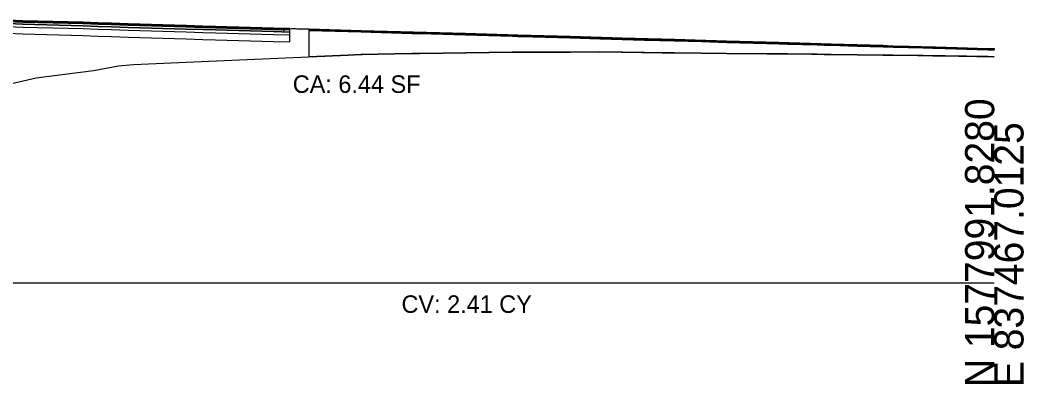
# Model space of a CAD drawing. Extents: x -26 to 6303, y -16 to 9563.
# Drawn here: x 2206.7 to 2302.8, y 4490.3 to 4525.2 of the extents above; entities that cross this region are included whole.
import ezdxf

# ---------------------------------------------------------------- set-up
doc = ezdxf.new("R2010")
doc.units = 0
for name, color, linetype in [('ASPHALT_19MM1', 7, 'Continuous'), ('ASPHALT_9_5MM1', 7, 'Continuous'), ('CONST_LV3', 7, 'Continuous'), ('Default', 7, 'Continuous'), ('DTM_P_FINISHED_GRADE', 7, 'Continuous'), ('DTM_P_FINISHED_GRADE2', 7, 'Continuous'), ('DTM_X_GROUND', 7, 'Continuous'), ('TRANS_PAVED_SHOULDERS', 7, 'Continuous'), ('XS_CELL', 7, 'Continuous'), ('XS_P_ASPHALT', 7, 'Continuous'), ('XS_P_SUBGRADE_GRANULAR', 7, 'Continuous'), ('XS_P_SUBGRADE_LEVELING', 7, 'Continuous'), ('XS_P_SUBGRADE_MILLING', 7, 'Continuous'), ('XS_SHEET_EW_TX_AREA', 7, 'Continuous'), ('XS_SHEET_EW_TX_VOLUME', 7, 'Continuous')]:
    doc.layers.add(name, color=color, linetype=linetype)

msp = doc.modelspace()

# ---------------------------------------------------------------- linework, layer by layer
at = {"layer": 'ASPHALT_19MM1'}
msp.add_lwpolyline([(2205.518, 4524.596), (2206.933, 4524.534), (2212.712, 4524.379), (2214.156, 4524.319), (2215.418, 4524.285), (2217.029, 4524.225), (2222.562, 4524.067), (2224.176, 4524.012), (2225.395, 4523.977), (2230.925, 4523.82), (2232.513, 4523.772), (2232.513, 4524.043), (2230.925, 4524.091), (2225.395, 4524.248), (2224.176, 4524.283), (2222.562, 4524.338), (2217.029, 4524.495), (2215.418, 4524.556), (2214.156, 4524.59), (2212.712, 4524.65), (2206.933, 4524.805), (2205.518, 4524.867)], dxfattribs=at)
at = {"layer": 'ASPHALT_9_5MM1'}
msp.add_lwpolyline([(2205.518, 4525.075), (2206.933, 4525.013), (2212.712, 4524.858), (2214.156, 4524.798), (2215.418, 4524.764), (2217.029, 4524.704), (2222.562, 4524.546), (2224.176, 4524.491), (2225.395, 4524.457), (2230.925, 4524.3), (2232.513, 4524.251), (2232.513, 4524.376), (2230.925, 4524.425), (2225.395, 4524.582), (2224.176, 4524.616), (2222.562, 4524.671), (2217.029, 4524.829), (2215.418, 4524.889), (2214.156, 4524.923), (2212.712, 4524.983), (2206.933, 4525.138), (2205.518, 4525.2)], dxfattribs=at)
at = {"layer": 'CONST_LV3'}
for points in [[(2205.518, 4523.928), (2206.933, 4523.867), (2212.712, 4523.711), (2214.156, 4523.651), (2215.418, 4523.618), (2217.029, 4523.557), (2222.562, 4523.4), (2224.176, 4523.345), (2225.395, 4523.31), (2230.925, 4523.153), (2232.513, 4523.105), (2232.513, 4524.376), (2230.925, 4524.424), (2225.395, 4524.581), (2224.176, 4524.615), (2222.562, 4524.671), (2217.029, 4524.828), (2215.418, 4524.888), (2214.156, 4524.922), (2212.712, 4524.982), (2206.933, 4525.137), (2205.518, 4525.199)], [(2289.363, 4522.762), (2284.361, 4522.904), (2279.359, 4523.046), (2274.357, 4523.188), (2269.355, 4523.33), (2264.353, 4523.472), (2259.351, 4523.614), (2254.349, 4523.756), (2249.347, 4523.898), (2244.345, 4524.04), (2239.343, 4524.182), (2234.341, 4524.324), (2233.08, 4524.359), (2232.662, 4524.371)]]:
    msp.add_lwpolyline(points, dxfattribs=at)
at = {"layer": 'Default'}
msp.add_lwpolyline([(2205.703, 4525.191), (2206.839, 4525.141), (2206.906, 4525.139), (2206.922, 4525.138), (2211.933, 4525.003), (2211.942, 4525.003), (2212.357, 4524.985), (2213.316, 4524.946), (2215.325, 4524.892), (2215.374, 4524.89), (2215.399, 4524.889), (2215.415, 4524.889), (2215.418, 4524.888), (2215.421, 4524.888), (2215.962, 4524.868), (2216.925, 4524.832), (2221.73, 4524.695), (2221.763, 4524.694), (2221.797, 4524.693), (2221.824, 4524.692), (2221.829, 4524.691), (2222.422, 4524.671), (2224.391, 4524.615), (2225.294, 4524.584), (2225.312, 4524.584), (2225.357, 4524.582), (2225.395, 4524.581), (2225.402, 4524.581), (2226.049, 4524.561), (2230.799, 4524.426), (2231.689, 4524.399), (2231.948, 4524.124)], dxfattribs=at)
at = {"layer": 'DTM_P_FINISHED_GRADE'}
msp.add_lwpolyline([(2205.518, 4525.199), (2206.933, 4525.137), (2212.712, 4524.982), (2214.156, 4524.922), (2215.418, 4524.888), (2217.029, 4524.828), (2222.562, 4524.671), (2224.176, 4524.615), (2225.395, 4524.581), (2230.925, 4524.424), (2232.513, 4524.376)], dxfattribs=at)
at = {"layer": 'DTM_P_FINISHED_GRADE2'}
msp.add_lwpolyline([(2205.518, 4525.199), (2206.933, 4525.137), (2212.712, 4524.982), (2214.156, 4524.922), (2215.418, 4524.888), (2217.029, 4524.828), (2222.562, 4524.671), (2224.176, 4524.615), (2225.395, 4524.581), (2228.11, 4524.5), (2233.187, 4524.356), (2234.341, 4524.324), (2236.216, 4524.27), (2239.343, 4524.182), (2241.232, 4524.128), (2244.345, 4524.04), (2246.249, 4523.986), (2249.347, 4523.898), (2251.267, 4523.843), (2254.349, 4523.756), (2256.286, 4523.701), (2259.351, 4523.614), (2261.306, 4523.558), (2264.353, 4523.472), (2266.328, 4523.416), (2269.355, 4523.33), (2271.346, 4523.274), (2274.347, 4523.188), (2274.351, 4523.188), (2274.357, 4523.188), (2276.375, 4523.131), (2279.359, 4523.046), (2280.851, 4523.004), (2283.04, 4522.942), (2283.573, 4522.927), (2284.361, 4522.904), (2286.429, 4522.846), (2289.363, 4522.762), (2289.747, 4522.751), (2290.301, 4522.736), (2291.882, 4522.691), (2294.115, 4522.627), (2294.217, 4522.625), (2294.365, 4522.62), (2296.459, 4522.561), (2299.367, 4522.478), (2300, 4522.46)], dxfattribs=at)
at = {"layer": 'DTM_X_GROUND'}
msp.add_lwpolyline([(2202.494, 4518.344), (2208.213, 4519.659), (2213.693, 4520.348), (2216.074, 4520.818), (2217.532, 4520.928), (2225.47, 4521.3), (2240.158, 4521.927), (2244.958, 4521.996), (2253.791, 4522.123), (2262.284, 4522.14), (2268.168, 4522.07), (2275.761, 4521.98), (2277.482, 4521.98), (2280.174, 4521.948), (2287.13, 4521.866), (2288.303, 4521.852), (2294.891, 4521.774), (2298.324, 4521.715), (2300, 4521.682)], dxfattribs=at)
at = {"layer": 'TRANS_PAVED_SHOULDERS'}
msp.add_lwpolyline([(2205.518, 4524.867), (2206.933, 4524.805), (2212.712, 4524.65), (2214.156, 4524.59), (2215.418, 4524.556), (2217.029, 4524.495), (2222.562, 4524.338), (2224.176, 4524.283), (2225.395, 4524.248), (2230.925, 4524.091), (2232.513, 4524.043), (2232.513, 4524.251), (2230.925, 4524.3), (2225.395, 4524.457), (2224.176, 4524.491), (2222.562, 4524.546), (2217.029, 4524.704), (2215.418, 4524.764), (2214.156, 4524.798), (2212.712, 4524.858), (2206.933, 4525.013), (2205.518, 4525.075)], dxfattribs=at)
at = {"layer": 'XS_CELL'}
msp.add_line((2150, 4500), (2300, 4500), dxfattribs=at)
at = {"layer": 'XS_P_ASPHALT'}
for points in [[(2205.518, 4525.199), (2206.933, 4525.137), (2212.712, 4524.982), (2214.156, 4524.922), (2215.418, 4524.888), (2217.029, 4524.828), (2222.562, 4524.671), (2224.176, 4524.615), (2225.395, 4524.581), (2230.925, 4524.424), (2232.513, 4524.376)], [(2300, 4522.46), (2300, 4522.335), (2300, 4522.335), (2299.367, 4522.353), (2299.367, 4522.353), (2296.459, 4522.436), (2296.459, 4522.436), (2294.365, 4522.495), (2294.365, 4522.495), (2294.217, 4522.5), (2294.217, 4522.5), (2294.115, 4522.502), (2294.115, 4522.502), (2291.882, 4522.566), (2291.882, 4522.566), (2290.301, 4522.611), (2290.301, 4522.611), (2289.747, 4522.626), (2289.747, 4522.626), (2289.363, 4522.637), (2289.363, 4522.637), (2286.429, 4522.721), (2286.429, 4522.721), (2284.361, 4522.779), (2284.361, 4522.779), (2283.573, 4522.802), (2283.573, 4522.802), (2283.04, 4522.817), (2283.04, 4522.817), (2280.851, 4522.879), (2280.851, 4522.879), (2279.359, 4522.921), (2279.359, 4522.921), (2276.375, 4523.006), (2276.375, 4523.006), (2274.357, 4523.063), (2274.357, 4523.063), (2274.351, 4523.063), (2274.351, 4523.063), (2274.347, 4523.063), (2274.347, 4523.063), (2271.346, 4523.149), (2271.346, 4523.149), (2269.355, 4523.205), (2269.355, 4523.205), (2266.328, 4523.291), (2266.328, 4523.291), (2264.353, 4523.347), (2264.353, 4523.347), (2261.306, 4523.433), (2261.306, 4523.433), (2259.351, 4523.489), (2259.351, 4523.489), (2256.286, 4523.576), (2256.286, 4523.576), (2254.349, 4523.631), (2254.349, 4523.631), (2251.267, 4523.718), (2251.267, 4523.718), (2249.347, 4523.773), (2249.347, 4523.773), (2246.249, 4523.861), (2246.249, 4523.861), (2244.345, 4523.915), (2244.345, 4523.915), (2241.232, 4524.003), (2241.232, 4524.003), (2239.343, 4524.057), (2239.343, 4524.057), (2236.216, 4524.145), (2236.216, 4524.145), (2234.341, 4524.199), (2234.341, 4524.199), (2234.341, 4524.245), (2234.341, 4524.245), (2234.341, 4524.324), (2234.341, 4524.324), (2236.216, 4524.27), (2236.216, 4524.27), (2239.343, 4524.182), (2239.343, 4524.182), (2241.232, 4524.128), (2241.232, 4524.128), (2244.345, 4524.04), (2244.345, 4524.04), (2246.249, 4523.986), (2246.249, 4523.986), (2249.347, 4523.898), (2249.347, 4523.898), (2251.267, 4523.843), (2251.267, 4523.843), (2254.349, 4523.756), (2254.349, 4523.756), (2256.286, 4523.701), (2256.286, 4523.701), (2259.351, 4523.614), (2259.351, 4523.614), (2261.306, 4523.558), (2261.306, 4523.558), (2264.353, 4523.472), (2264.353, 4523.472), (2266.328, 4523.416), (2266.328, 4523.416), (2269.355, 4523.33), (2269.355, 4523.33), (2271.346, 4523.274), (2271.346, 4523.274), (2274.347, 4523.188), (2274.347, 4523.188), (2274.351, 4523.188), (2274.351, 4523.188), (2274.357, 4523.188), (2274.357, 4523.188), (2276.375, 4523.131), (2276.375, 4523.131), (2279.359, 4523.046), (2279.359, 4523.046), (2280.851, 4523.004), (2280.851, 4523.004), (2283.04, 4522.942), (2283.04, 4522.942), (2283.573, 4522.927), (2283.573, 4522.927), (2284.361, 4522.904), (2284.361, 4522.904), (2286.429, 4522.846), (2286.429, 4522.846), (2289.363, 4522.762), (2289.363, 4522.762), (2289.747, 4522.751), (2289.747, 4522.751), (2290.301, 4522.736), (2290.301, 4522.736), (2291.882, 4522.691), (2291.882, 4522.691), (2294.115, 4522.627), (2294.115, 4522.627), (2294.217, 4522.625), (2294.217, 4522.625), (2294.365, 4522.62), (2294.365, 4522.62), (2296.459, 4522.561), (2296.459, 4522.561), (2299.367, 4522.478), (2299.367, 4522.478), (2300, 4522.46)]]:
    msp.add_lwpolyline(points, dxfattribs=at)
at = {"layer": 'XS_P_SUBGRADE_GRANULAR'}
msp.add_lwpolyline([(2205.518, 4523.928), (2206.933, 4523.867), (2212.712, 4523.711), (2214.156, 4523.651), (2215.418, 4523.618), (2217.029, 4523.557), (2222.562, 4523.4), (2224.176, 4523.345), (2225.395, 4523.31), (2230.925, 4523.153), (2232.513, 4523.105)], dxfattribs=at)
at = {"layer": 'XS_P_SUBGRADE_LEVELING'}
msp.add_lwpolyline([(2300, 4521.682), (2299.367, 4521.694), (2295.283, 4521.766), (2294.365, 4521.78), (2294.32, 4521.781), (2294.115, 4521.783), (2293.18, 4521.794), (2290.301, 4521.828), (2289.836, 4521.834), (2289.363, 4521.84), (2286.85, 4521.869), (2284.361, 4521.899), (2283.698, 4521.906), (2283.04, 4521.914), (2280.174, 4521.948), (2279.359, 4521.958), (2278.213, 4521.962), (2274.357, 4521.997), (2274.352, 4521.997), (2274.347, 4521.997), (2271.935, 4522.025), (2269.355, 4522.056), (2266.484, 4522.09), (2264.353, 4522.115), (2262.216, 4522.139), (2259.351, 4522.134), (2254.596, 4522.124), (2254.349, 4522.124), (2253.791, 4522.123), (2249.347, 4522.059), (2244.958, 4521.996), (2244.345, 4521.987), (2244.185, 4521.984), (2239.343, 4521.892), (2238.087, 4521.838), (2234.341, 4521.679), (2234.341, 4523.395), (2234.341, 4524.199), (2238.087, 4524.092), (2239.343, 4524.057), (2244.185, 4523.919), (2244.345, 4523.915), (2244.958, 4523.897), (2249.347, 4523.773), (2253.791, 4523.647), (2254.349, 4523.631), (2254.596, 4523.624), (2259.351, 4523.489), (2262.216, 4523.408), (2264.353, 4523.347), (2266.484, 4523.287), (2269.355, 4523.205), (2271.935, 4523.132), (2274.347, 4523.063), (2274.352, 4523.063), (2274.357, 4523.063), (2278.213, 4522.954), (2279.359, 4522.921), (2280.174, 4522.898), (2283.04, 4522.817), (2283.698, 4522.798), (2284.361, 4522.779), (2286.85, 4522.709), (2289.363, 4522.637), (2289.836, 4522.624), (2290.301, 4522.611), (2293.18, 4522.529), (2294.115, 4522.503), (2294.32, 4522.497), (2294.365, 4522.495), (2295.283, 4522.469), (2299.367, 4522.353), (2300, 4522.335)], dxfattribs=at)
at = {"layer": 'XS_P_SUBGRADE_MILLING'}
msp.add_lwpolyline([(2300, 4521.682), (2299.367, 4521.694), (2295.283, 4521.766), (2294.365, 4521.78), (2294.32, 4521.781), (2294.115, 4521.783), (2293.18, 4521.794), (2290.301, 4521.828), (2289.836, 4521.834), (2289.363, 4521.84), (2286.85, 4521.869), (2284.361, 4521.899), (2283.698, 4521.906), (2283.04, 4521.914), (2280.174, 4521.948), (2279.359, 4521.958), (2278.213, 4521.962), (2274.357, 4521.997), (2274.352, 4521.997), (2274.347, 4521.997), (2271.935, 4522.025), (2269.355, 4522.056), (2266.484, 4522.09), (2264.353, 4522.115), (2262.216, 4522.139), (2259.351, 4522.134), (2254.596, 4522.124), (2254.349, 4522.124), (2253.791, 4522.123), (2249.347, 4522.059), (2244.958, 4521.996), (2244.345, 4521.987), (2244.185, 4521.984), (2239.343, 4521.892), (2238.087, 4521.838), (2234.341, 4521.679), (2234.341, 4521.679), (2234.341, 4521.679), (2238.087, 4521.838), (2239.343, 4521.892), (2244.185, 4521.984), (2244.345, 4521.987), (2244.958, 4521.996), (2249.347, 4522.059), (2253.791, 4522.123), (2254.349, 4522.124), (2254.596, 4522.124), (2259.351, 4522.134), (2262.216, 4522.139), (2264.353, 4522.115), (2266.484, 4522.09), (2269.355, 4522.056), (2271.935, 4522.025), (2274.347, 4521.997), (2274.352, 4521.997), (2274.357, 4521.997), (2278.213, 4521.962), (2279.359, 4521.958), (2280.174, 4521.948), (2283.04, 4521.914), (2283.698, 4521.907), (2284.361, 4521.899), (2286.85, 4521.869), (2289.363, 4521.84), (2289.836, 4521.834), (2290.301, 4521.828), (2293.18, 4521.794), (2294.115, 4521.783), (2294.32, 4521.781), (2294.365, 4521.78), (2295.283, 4521.766), (2299.367, 4521.694), (2300, 4521.682)], dxfattribs=at)

# ---------------------------------------------------------------- texts
at = {"layer": 'XS_CELL'}
for s, p in [('N 1577991.8280', (2300, 4490)), ('E 837467.0125', (2302.8, 4490))]:
    msp.add_text(s, height=2.8, rotation=90, dxfattribs=at).set_placement(p)
at = {"layer": 'XS_SHEET_EW_TX_AREA'}
msp.add_text('CA: 6.44 SF', height=1.68, dxfattribs=at).set_placement((2232.786, 4518.216))
at = {"layer": 'XS_SHEET_EW_TX_VOLUME'}
msp.add_text('CV: 2.41 CY', height=1.68, dxfattribs=at).set_placement((2243.203, 4497.12))

doc.saveas('drawing.dxf')
